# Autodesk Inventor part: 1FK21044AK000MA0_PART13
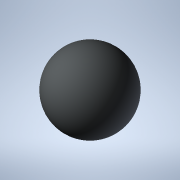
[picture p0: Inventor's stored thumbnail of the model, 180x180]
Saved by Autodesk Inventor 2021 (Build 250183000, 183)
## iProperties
Created: 2025-04
Part Number: 1FK21044AK000MA0_PART13
Material: Generic
Catalog Web Link: www.3dfindit.com
Description: -Servo synchronous motor
Document SubType Name: Modeling
Designer: psAdmin
Mass: 0.137258 g
Surface Area: 1.2868 cm^2
Volume: 0.137258 cm^3
Density: 1 g/cm^3
Appearance: PSOLRGB-212-217-219
Category: PARTsolutions
Title: 1FK21044AK000MA0_PART13
Author: Cadenas PARTsolutions
Comments: Servo synchronous motor
Sending System: PARTsolutions
Preprocessor: ST-DEVELOPER v19.3
PSOL_IDENT_0: {$CADENAS_DATA/23d-libs/siemens_ag/_cat_/87/f4/1fk21044ak000ma0.prj},216 {VTYP=3D},{NB=1FK21044AK000
PSOL_IDENT_1: MA0_PART13},{LINA=1FK21044AK000MA0_PART13},{NN=1FK21044AK000MA0_PART13},{NOPRJ=TRUE},{DATE=19.08.202
PSOL_IDENT_2: 5 14:00:48},{GEOMDATE=30.07.2025 02:00:50},{VERSION=},{LINEID=10},{WBVAR=},{WBNUMERIC=}  {NB=1FK2104
PSOL_IDENT_3: 4AK000MA0_PART13},{LINA=1FK21044AK000MA0_PART13},{KT=DUMMY},{PREVIEW=../../../_pool_/cb/72/p_d211_xx
PSOL_IDENT_4: _00434j.png},{DESCSHORT=SIMOTICS S-1FK2 HD, SINAMICS S210 3AC 400V-480V, 0.95 Nm, 6000 rpm},{DESCLON
PSOL_IDENT_5: G=SIMOTICS S-1FK2 HD servo motor M0=1.27 Nm; PN = 0.6 kW at nN=6000 rpm (380-480 V); PN = 0.4 kW at
PSOL_IDENT_6: nN=3000 rpm (200-240 V); degree of protection IP64; cylindrical shaft D19x40mm; absolute encoder 22-
PSOL_IDENT_7: bit + 12-bit multiturn (encoder AM22DQC); with OCC interface; plug size M17, rotatable; SIMOTICS S-1
PSOL_IDENT_8: FK2 servomotorfor a wide range of uses in industrial environments. SIMOTICS S‑1FK2 servomotors are c
PSOL_IDENT_9: ompact synchronous motors with a high dynamic performance that set themselves apart as a result of t
PSOL_IDENT_10: heir high power density, degree of protection and overload capability. The motors are available in t
PSOL_IDENT_11: wo variants: as High Dynamic variant (highest dynamic performance as a result of the low intrinsic m
PSOL_IDENT_12: oment of inertia for applications demanding a high dynamic performance with low moved masses) - and
PSOL_IDENT_13: as Compact variant (precise and stable closed-loop control for medium up to large moved masses as a
PSOL_IDENT_14: result of a medium intrinsic moment of inertia). SIMOTICSS‑1FK2 servomotors fully exploit their stre
PSOL_IDENT_15: ngths in a system with the SINAMICSS210 frequency converter and simple connection using the one cabl
PSOL_IDENT_16: e connection (OCC). Advantages include the short control and positioning times, fast and precise cor
PSOL_IDENT_17: rection of disturbing quantities as well as stable control with a high dynamic performance. The serv
PSOL_IDENT_18: o motors can be configured to address a wide range of requirements. For example with and without hol
PSOL_IDENT_19: ding brake, IP64 or IP65 degree of protection, singleturn or multiturn absolute encoders - to name j
PSOL_IDENT_20: ust a few. Further, the servomotors are available in different shaft heights extending from 20 to 10
PSOL_IDENT_21: 0. A shaft sealing ring is available to achieve an IP65 degree of protection and for subsequent moun
PSOL_IDENT_22: ting at the motor or as spare part. SIMOTICS - the optimum motor for each and every motion control a
PSOL_IDENT_23: pplication.},{INTNO=195125056312},{SUPPLIERALTNO=1FK2104-4AK00-0MA0},{MANUID=1FK21044AK000MA0},{MANU
PSOL_IDENT_24: NAME=Siemens},{MANUTYPEDESC=Synchronous motor 1FK2-HD 1,27 Nm},{AAU732=SIMOTICS},{AAO057=S-1FK2},{AA
PSOL_IDENT_25: U734=SIMOTICS S-1FK2 HD servo motor M0=1.27 Nm; PN = 0.6 kW at nN=6000 rpm (380-480 V); PN = 0.4 kW
PSOL_IDENT_26: at nN=3000 rpm (200-240 V); degree of protection IP64; cylindrical shaft D19x40mm; absolute encoder
PSOL_IDENT_27: 22-bit + 12-bit multiturn (encoder AM22DQC); with OCC interface; plug size M17, rotatable;},{AAW338=
PSOL_IDENT_28: Synchronous motor 1FK2-HD 1,27 Nm},{AAO742=SIMOTICS},{AAO663=4042948690994},{NOCUPEROU=1},{PRICEQUAN
PSOL_IDENT_29: TITY=1},{QUANTITYMIN=1},{QUANTITYINT=1},{CTN=85015100},{COO=DE},{AAO676=1FK2104-4AK00-0MA0},{AAO677=
PSOL_IDENT_30: Siemens AG},{ORDERUNIT=C62},{CONTENTUNIT=C62}
NB: 1FK21044AK000MA0_PART13
NT: Servo synchronous motor
NBSYN: $MANUID._PART13
LINA: 1FK21044AK000MA0_PART13
CATALOG: SIEMENS
PREVIEW: ../../../_pool_/cb/72/p_d211_xx_00434j.png
DESCSHORT: SIMOTICS S-1FK2 HD, SINAMICS S210 3AC 400V-480V, 0.95 Nm, 6000 rpm
DESCLONG: SIMOTICS S-1FK2 HD servo motor M0=1.27 Nm; PN = 0.6 kW at nN=6000 rpm (380-480 V); PN = 0.4 kW at nN=3000 rpm (200-240 V); degree of protection IP64; cylindrica
INTNO: 195125056312
SUPPLIERALTNO: 1FK2104-4AK00-0MA0
MANUID: 1FK21044AK000MA0
MANUNAME: Siemens
MANUTYPEDESC: Synchronous motor 1FK2-HD 1,27 Nm
AAU732: SIMOTICS
AAO057: S-1FK2
AAU734: SIMOTICS S-1FK2 HD servo motor M0=1.27 Nm; PN = 0.6 kW at nN=6000 rpm (380-480 V); PN = 0.4 kW at nN=3000 rpm (200-240 V); degree of protection IP64; cylindrica
AAW338: Synchronous motor 1FK2-HD 1,27 Nm
AAO742: SIMOTICS
AAO663: 4042948690994.0
NOCUPEROU: 1
PRICEQUANTITY: 1
QUANTITYMIN: 1
QUANTITYINT: 1
CTN: 85015100
COO: DE
ARTICLENO: 1FK21044AK000MA0_PART13
BOMINFO: 1FK21044AK000MA0_PART13
CREATOR: CADENAS GmbH
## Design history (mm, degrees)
feature "2025_04_17_15_37_40_0588"
body "Solid1"
